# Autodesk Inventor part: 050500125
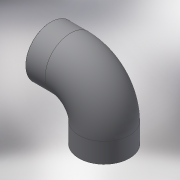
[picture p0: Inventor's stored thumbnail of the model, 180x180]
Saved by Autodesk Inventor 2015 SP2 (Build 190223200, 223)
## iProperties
Created: 2017-10
Part Number: 050500125
Material: Generic
Description: PLASSON 90° ELBOW-CEMENT PVC 125
Document SubType Name: Modeling
Designer: KIM
Density: 1 g/cm^3
Appearance: Default
Author: KIM
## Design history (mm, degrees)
derived "050500.ipt"
feature "Solid1::050500.ipt"
tag "TaggingFeature1"
body "Solid1"
other parameters: "d1" = 148, "d4" = 125, "d5" = 112.5, "d7" = 1.25, "d9" = 148, "d10" = 137, "d13" = 90 deg, "d18" = 66, "d19" = 90 deg, "d20" = 125, "d21" = 69, "d22" = 0, "d24" = 90 deg, "d26" = 112.5, "d27" = 90 deg, "d_" = 125, "E_" = 148, "H_" = 211, "l_" = 69, "Z_" = 66
